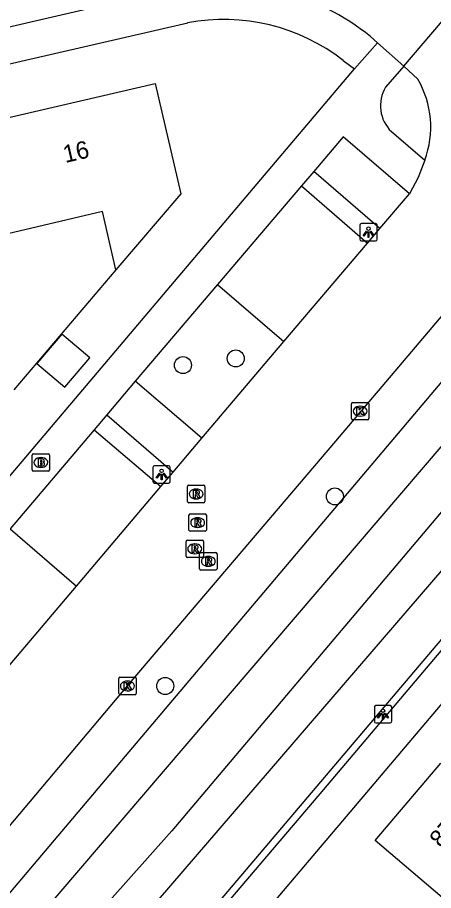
# Model space of a CAD drawing. Extents: x 156414 to 157775, y 382335 to 383765.
# Drawn here: x 156837.1 to 156861, y 382528.4 to 382578.5 of the extents above; entities that cross this region are included whole.
import ezdxf

# ---------------------------------------------------------------- set-up
doc = ezdxf.new("R2010")
doc.units = 0
for name, color, linetype in [('IMGEO_Boom', 7, 'Continuous'), ('IMGEO_Brandkraan', 7, 'Continuous'), ('IMGEO_Groenvoorziening', 7, 'Continuous'), ('IMGEO_Haag', 7, 'Continuous'), ('IMGEO_Kolk', 7, 'Continuous'), ('IMGEO_Lichtpunt', 7, 'Continuous'), ('IMGEO_Muur', 7, 'Continuous'), ('IMGEO_Pand', 7, 'Continuous'), ('IMGEO_Pand_nummerreeks', 7, 'Continuous'), ('IMGEO_Parkeervlak_open', 7, 'Continuous'), ('IMGEO_Rijbaan_lokaal_gesloten', 7, 'Continuous'), ('IMGEO_Rioolput', 7, 'Continuous'), ('IMGEO_Voetpad_open', 7, 'Continuous'), ('IMGEO_Waterloop', 7, 'Continuous')]:
    doc.layers.add(name, color=color, linetype=linetype)

msp = doc.modelspace()

# ---------------------------------------------------------------- linework, layer by layer
at = {"layer": 'IMGEO_Boom'}
for centre in [(156849.67, 382558.967), (156846.64, 382558.585), (156855.363, 382551.053), (156845.62, 382540.18)]:
    msp.add_circle(centre, 0.489, dxfattribs=at)
at = {"layer": 'IMGEO_Brandkraan'}
for p, q in [((156837.98, 382552.575), (156837.98, 382553.427)), ((156838.055, 382553.501), (156838.907, 382553.501)), ((156838.468, 382553.281), (156838.493, 382553.281)), ((156838.981, 382553.427), (156838.981, 382552.575)), ((156838.491, 382552.721), (156838.466, 382552.721)), ((156838.907, 382552.501), (156838.055, 382552.501))]:
    msp.add_line(p, q, dxfattribs=at)
for points in [[(156837.98, 382552.575), (156837.98, 382553.427)], [(156838.055, 382553.501), (156838.907, 382553.501)], [(156838.328, 382553.201), (156838.328, 382552.801), (156838.541, 382552.801)], [(156838.559, 382553.201), (156838.328, 382553.201)], [(156838.507, 382553.12), (156838.453, 382553.12), (156838.453, 382553.044)], [(156838.981, 382553.427), (156838.981, 382552.575)], [(156838.453, 382553.044), (156838.506, 382553.044)], [(156838.515, 382552.968), (156838.453, 382552.968), (156838.453, 382552.887)], [(156838.453, 382552.887), (156838.515, 382552.887)], [(156838.907, 382552.501), (156838.055, 382552.501)]]:
    msp.add_lwpolyline(points, dxfattribs=at)
for centre, radius, start, end in [((156838.057, 382553.425), 0.0765, 91.552, 178.448), ((156838.057, 382553.425), 0.0765, 91.552, 178.448), ((156838.508, 382553.082), 0.0379, 267.8285, 90.9355), ((156838.563, 382553.056), 0.145, 59.4692, 91.5367), ((156838.588, 382553.103), 0.0922, 285.5137, 58.1501), ((156838.905, 382553.425), 0.0765, 1.552, 88.448), ((156838.905, 382553.425), 0.0765, 1.552, 88.448), ((156838.516, 382552.927), 0.0404, 269.8759, 90.5077), ((156838.547, 382553.052), 0.251, 268.6676, 293.5347), ((156838.593, 382552.911), 0.105, 301.3115, 78.989), ((156838.057, 382552.577), 0.0765, 181.552, 268.448), ((156838.057, 382552.577), 0.0765, 181.552, 268.448), ((156838.905, 382552.577), 0.0765, 271.552, 358.448), ((156838.905, 382552.577), 0.0765, 271.552, 358.448)]:
    msp.add_arc(centre, radius, start, end, dxfattribs=at)
for centre, major_axis, ratio, start_param, end_param in [((156838.467, 382553.001), (-0.387, 0.002), 0.722429, 4.712389, 7.853982), ((156838.492, 382553.001), (-0.39, 0.002), 0.717154, 1.570796, 4.712389)]:
    msp.add_ellipse(centre, major_axis=major_axis, ratio=ratio, start_param=start_param, end_param=end_param, dxfattribs=at)
at = {"layer": 'IMGEO_Groenvoorziening'}
for points in [[(156883.467, 382582.632), (156865.157, 382561.969), (156834.624, 382525.907), (156833.429, 382523.914), (156832.515, 382522.224)], [(156836.701, 382518.344), (156839.563, 382521.34), (156866.603, 382552.72), (156888.158, 382578.673)]]:
    msp.add_lwpolyline(points, dxfattribs=at)
at = {"layer": 'IMGEO_Haag'}
msp.add_lwpolyline([(156890.335, 382576.835), (156839.257, 382516.694), (156839.538, 382516.434), (156839.658, 382516.575)], dxfattribs=at)
at = {"layer": 'IMGEO_Kolk'}
for p, q in [((156856.311, 382555.52), (156856.311, 382556.372)), ((156856.386, 382556.446), (156857.238, 382556.446)), ((156856.799, 382556.226), (156856.824, 382556.226)), ((156857.312, 382556.372), (156857.312, 382555.52)), ((156856.822, 382555.666), (156856.797, 382555.666)), ((156857.238, 382555.446), (156856.386, 382555.446)), ((156842.947, 382539.757), (156842.947, 382540.609)), ((156843.022, 382540.683), (156843.874, 382540.683)), ((156843.948, 382540.609), (156843.948, 382539.757)), ((156843.435, 382540.463), (156843.46, 382540.463)), ((156843.874, 382539.683), (156843.022, 382539.683)), ((156843.458, 382539.903), (156843.433, 382539.903))]:
    msp.add_line(p, q, dxfattribs=at)
for points in [[(156856.311, 382555.52), (156856.311, 382556.372)], [(156856.386, 382556.446), (156857.238, 382556.446)], [(156856.632, 382556.146), (156856.755, 382556.146), (156856.755, 382555.995), (156856.885, 382556.146), (156857.049, 382556.146), (156856.903, 382555.995), (156857.056, 382555.746), (156856.904, 382555.746), (156856.819, 382555.91), (156856.755, 382555.843), (156856.755, 382555.746), (156856.632, 382555.746), (156856.632, 382556.146)], [(156857.312, 382556.372), (156857.312, 382555.52)], [(156857.238, 382555.446), (156856.386, 382555.446)], [(156842.947, 382539.757), (156842.947, 382540.609)], [(156843.022, 382540.683), (156843.874, 382540.683)], [(156843.948, 382540.609), (156843.948, 382539.757)], [(156843.268, 382540.383), (156843.391, 382540.383), (156843.391, 382540.232), (156843.521, 382540.383), (156843.685, 382540.383), (156843.539, 382540.232), (156843.692, 382539.983), (156843.54, 382539.983), (156843.455, 382540.147), (156843.391, 382540.08), (156843.391, 382539.983), (156843.268, 382539.983), (156843.268, 382540.383)], [(156843.874, 382539.683), (156843.022, 382539.683)]]:
    msp.add_lwpolyline(points, dxfattribs=at)
for centre, start, end in [((156856.388, 382556.37), 91.552, 178.448), ((156856.388, 382556.37), 91.552, 178.448), ((156857.236, 382556.37), 1.552, 88.448), ((156857.236, 382556.37), 1.552, 88.448), ((156856.388, 382555.522), 181.552, 268.448), ((156856.388, 382555.522), 181.552, 268.448), ((156857.236, 382555.522), 271.552, 358.448), ((156857.236, 382555.522), 271.552, 358.448), ((156843.024, 382540.607), 91.552, 178.448), ((156843.024, 382540.607), 91.552, 178.448), ((156843.872, 382540.607), 1.552, 88.448), ((156843.872, 382540.607), 1.552, 88.448), ((156843.024, 382539.759), 181.552, 268.448), ((156843.024, 382539.759), 181.552, 268.448), ((156843.872, 382539.759), 271.552, 358.448), ((156843.872, 382539.759), 271.552, 358.448)]:
    msp.add_arc(centre, 0.0765, start, end, dxfattribs=at)
for centre, major_axis, ratio, start_param, end_param in [((156856.798, 382555.946), (-0.387, 0.002), 0.722429, 4.712389, 7.853982), ((156856.823, 382555.946), (-0.39, 0.002), 0.717154, 1.570796, 4.712389), ((156843.434, 382540.183), (-0.387, 0.002), 0.722429, 4.712389, 7.853982), ((156843.459, 382540.183), (-0.39, 0.002), 0.717154, 1.570796, 4.712389)]:
    msp.add_ellipse(centre, major_axis=major_axis, ratio=ratio, start_param=start_param, end_param=end_param, dxfattribs=at)
at = {"layer": 'IMGEO_Lichtpunt'}
for p, q in [((156857.698, 382566.708), (156856.89, 382566.708)), ((156857.698, 382566.708), (156856.89, 382566.708)), ((156856.796, 382566.613), (156856.796, 382565.806)), ((156856.796, 382566.613), (156856.796, 382565.806)), ((156857.792, 382565.806), (156857.792, 382566.613)), ((156857.792, 382565.806), (156857.792, 382566.613)), ((156856.89, 382565.712), (156857.698, 382565.712)), ((156856.89, 382565.712), (156857.698, 382565.712)), ((156844.913, 382552.721), (156844.913, 382551.914)), ((156844.913, 382552.721), (156844.913, 382551.914)), ((156845.815, 382552.816), (156845.007, 382552.816)), ((156845.815, 382552.816), (156845.007, 382552.816)), ((156845.909, 382551.914), (156845.909, 382552.721)), ((156845.909, 382551.914), (156845.909, 382552.721)), ((156845.007, 382551.82), (156845.815, 382551.82)), ((156845.007, 382551.82), (156845.815, 382551.82)), ((156857.629, 382538.966), (156857.629, 382538.159)), ((156857.629, 382538.966), (156857.629, 382538.159)), ((156858.531, 382539.061), (156857.723, 382539.061)), ((156858.531, 382539.061), (156857.723, 382539.061)), ((156858.625, 382538.159), (156858.625, 382538.966)), ((156858.625, 382538.159), (156858.625, 382538.966)), ((156857.723, 382538.065), (156858.531, 382538.065)), ((156857.723, 382538.065), (156858.531, 382538.065))]:
    msp.add_line(p, q, dxfattribs=at)
for points in [[(156857.17, 382566.277), (156857.209, 382566.249), (156857.021, 382565.987), (156856.983, 382566.014), (156857.17, 382566.277)], [(156857.272, 382566.229), (156857.319, 382566.229), (156857.319, 382565.907), (156857.272, 382565.907), (156857.272, 382566.229)], [(156857.382, 382566.249), (156857.42, 382566.276), (156857.607, 382566.014), (156857.568, 382565.986), (156857.382, 382566.249)], [(156845.287, 382552.385), (156845.326, 382552.357), (156845.138, 382552.095), (156845.1, 382552.122), (156845.287, 382552.385)], [(156845.389, 382552.337), (156845.436, 382552.337), (156845.436, 382552.015), (156845.389, 382552.015), (156845.389, 382552.337)], [(156845.499, 382552.357), (156845.537, 382552.384), (156845.724, 382552.122), (156845.685, 382552.094), (156845.499, 382552.357)], [(156858.003, 382538.63), (156858.042, 382538.602), (156857.854, 382538.34), (156857.816, 382538.367), (156858.003, 382538.63)], [(156858.215, 382538.602), (156858.253, 382538.629), (156858.44, 382538.367), (156858.401, 382538.339), (156858.215, 382538.602)], [(156858.105, 382538.582), (156858.152, 382538.582), (156858.152, 382538.26), (156858.105, 382538.26), (156858.105, 382538.582)]]:
    msp.add_lwpolyline(points, dxfattribs=at)
for centre in [(156857.295, 382566.411), (156845.412, 382552.519), (156858.128, 382538.764)]:
    msp.add_circle(centre, 0.0994, dxfattribs=at)
for centre, start, end in [((156856.89, 382566.613), 90, 180), ((156856.89, 382566.613), 90, 180), ((156857.698, 382566.613), 0, 90), ((156857.698, 382566.613), 0, 90), ((156856.89, 382565.806), 180, 270), ((156856.89, 382565.806), 180, 270), ((156857.698, 382565.806), 270, 0), ((156857.698, 382565.806), 270, 360), ((156845.007, 382552.721), 90, 180), ((156845.007, 382552.721), 90, 180), ((156845.815, 382552.721), 0, 90), ((156845.815, 382552.721), 0, 90), ((156845.007, 382551.914), 180, 270), ((156845.007, 382551.914), 180, 270), ((156845.815, 382551.914), 270, 0), ((156845.815, 382551.914), 270, 360), ((156857.723, 382538.966), 90, 180), ((156857.723, 382538.966), 90, 180), ((156858.531, 382538.966), 0, 90), ((156858.531, 382538.966), 0, 90), ((156857.723, 382538.159), 180, 270), ((156857.723, 382538.159), 180, 270), ((156858.531, 382538.159), 270, 0), ((156858.531, 382538.159), 270, 360)]:
    msp.add_arc(centre, 0.0946, start, end, dxfattribs=at)
at = {"layer": 'IMGEO_Muur'}
msp.add_lwpolyline([(156842.791, 382564.053), (156836.926, 382557.168)], dxfattribs=at)
at = {"layer": 'IMGEO_Pand'}
for points in [[(156835.122, 382572.451), (156845.049, 382574.744), (156846.509, 382568.408), (156842.791, 382564.053), (156842.016, 382567.39), (156836.576, 382566.122)], [(156838.256, 382558.675), (156839.859, 382557.315), (156841.294, 382559.006), (156839.692, 382560.366), (156838.256, 382558.675)], [(156869.14, 382529.214), (156865.381, 382524.784), (156857.671, 382531.315), (156861.441, 382535.754)]]:
    msp.add_lwpolyline(points, dxfattribs=at)
at = {"layer": 'IMGEO_Parkeervlak_open'}
for points in [[(156848.622, 382563.205), (156852.423, 382559.947)], [(156847.72, 382554.39), (156843.897, 382557.663)], [(156836.723, 382549.204), (156840.532, 382545.9)]]:
    msp.add_lwpolyline(points, dxfattribs=at)
at = {"layer": 'IMGEO_Rijbaan_lokaal_gesloten'}
for points in [[(156881.147, 382584.59), (156855.391, 382554.226), (156843.769, 382540.567), (156831.328, 382525.852), (156828.33, 382522.305), (156828.27, 382522.229), (156828.21, 382522.153)], [(156846.459, 382580.188), (156845.95, 382580.133), (156762.402, 382560.842)], [(156859.329, 382575.743), (156862.534, 382579.499)], [(156857.81, 382577.079), (156857.405, 382577.435)], [(156857.81, 382577.079), (156859.329, 382575.743)], [(156860.125, 382574.983), (156859.329, 382575.743)], [(156860.522, 382570.35), (156860.138, 382569.338), (156859.65, 382568.411)], [(156857.952, 382566.422), (156859.65, 382568.411)], [(156857.228, 382565.575), (156857.952, 382566.422)], [(156852.423, 382559.947), (156857.228, 382565.575)], [(156847.72, 382554.39), (156852.423, 382559.947)], [(156846.072, 382552.444), (156847.72, 382554.39)], [(156845.373, 382551.618), (156846.072, 382552.444)], [(156840.532, 382545.9), (156845.373, 382551.618)], [(156836.503, 382541.171), (156840.532, 382545.9)]]:
    msp.add_lwpolyline(points, dxfattribs=at)
for centre, radius, start, end in [((156848.965, 382567.013), 13.411, 50.9975, 100.7675), ((156855.491, 382572.252), 5.379, 339.2865, 30.5088)]:
    msp.add_arc(centre, radius, start, end, dxfattribs=at)
at = {"layer": 'IMGEO_Rioolput'}
for p, q in [((156846.895, 382550.768), (156846.895, 382551.62)), ((156846.97, 382551.694), (156847.822, 382551.694)), ((156847.896, 382551.62), (156847.896, 382550.768)), ((156847.383, 382551.474), (156847.408, 382551.474)), ((156847.822, 382550.694), (156846.97, 382550.694)), ((156847.406, 382550.914), (156847.381, 382550.914)), ((156846.982, 382549.127), (156846.982, 382549.979)), ((156847.057, 382550.053), (156847.909, 382550.053)), ((156847.47, 382549.833), (156847.495, 382549.833)), ((156847.983, 382549.979), (156847.983, 382549.127)), ((156847.493, 382549.273), (156847.468, 382549.273)), ((156847.909, 382549.053), (156847.057, 382549.053)), ((156846.814, 382547.623), (156846.814, 382548.475)), ((156846.889, 382548.549), (156847.741, 382548.549)), ((156847.302, 382548.329), (156847.327, 382548.329)), ((156847.815, 382548.475), (156847.815, 382547.623)), ((156847.325, 382547.769), (156847.3, 382547.769)), ((156847.594, 382546.906), (156847.594, 382547.758)), ((156847.669, 382547.832), (156848.521, 382547.832)), ((156848.082, 382547.612), (156848.107, 382547.612)), ((156848.595, 382547.758), (156848.595, 382546.906)), ((156847.741, 382547.549), (156846.889, 382547.549)), ((156848.521, 382546.832), (156847.669, 382546.832)), ((156848.105, 382547.052), (156848.08, 382547.052))]:
    msp.add_line(p, q, dxfattribs=at)
for points in [[(156846.895, 382550.768), (156846.895, 382551.62)], [(156846.97, 382551.694), (156847.822, 382551.694)], [(156847.896, 382551.62), (156847.896, 382550.768)], [(156847.484, 382551.392), (156847.232, 382551.394), (156847.232, 382550.994)], [(156847.232, 382550.994), (156847.356, 382550.994), (156847.356, 382551.156), (156847.367, 382551.156)], [(156847.41, 382551.313), (156847.356, 382551.313), (156847.356, 382551.232)], [(156847.356, 382551.232), (156847.408, 382551.232)], [(156847.414, 382551.127), (156847.485, 382550.994), (156847.625, 382550.994), (156847.56, 382551.12)], [(156847.822, 382550.694), (156846.97, 382550.694)], [(156846.982, 382549.127), (156846.982, 382549.979)], [(156847.057, 382550.053), (156847.909, 382550.053)], [(156847.571, 382549.751), (156847.319, 382549.753), (156847.319, 382549.353)], [(156847.497, 382549.672), (156847.443, 382549.672), (156847.443, 382549.591)], [(156847.983, 382549.979), (156847.983, 382549.127)], [(156847.319, 382549.353), (156847.443, 382549.353), (156847.443, 382549.515), (156847.454, 382549.515)], [(156847.443, 382549.591), (156847.495, 382549.591)], [(156847.501, 382549.486), (156847.572, 382549.353), (156847.712, 382549.353), (156847.647, 382549.479)], [(156847.909, 382549.053), (156847.057, 382549.053)], [(156846.814, 382547.623), (156846.814, 382548.475)], [(156846.889, 382548.549), (156847.741, 382548.549)], [(156847.403, 382548.247), (156847.151, 382548.249), (156847.151, 382547.849)], [(156847.329, 382548.168), (156847.275, 382548.168), (156847.275, 382548.087)], [(156847.815, 382548.475), (156847.815, 382547.623)], [(156847.151, 382547.849), (156847.275, 382547.849), (156847.275, 382548.011), (156847.286, 382548.011)], [(156847.275, 382548.087), (156847.327, 382548.087)], [(156847.333, 382547.982), (156847.404, 382547.849), (156847.544, 382547.849), (156847.479, 382547.975)], [(156847.594, 382546.906), (156847.594, 382547.758)], [(156847.669, 382547.832), (156848.521, 382547.832)], [(156848.595, 382547.758), (156848.595, 382546.906)], [(156847.741, 382547.549), (156846.889, 382547.549)], [(156848.183, 382547.53), (156847.931, 382547.532), (156847.931, 382547.132)], [(156847.931, 382547.132), (156848.055, 382547.132), (156848.055, 382547.294), (156848.066, 382547.294)], [(156848.109, 382547.451), (156848.055, 382547.451), (156848.055, 382547.37)], [(156848.055, 382547.37), (156848.107, 382547.37)], [(156848.113, 382547.265), (156848.184, 382547.132), (156848.324, 382547.132), (156848.259, 382547.258)], [(156848.521, 382546.832), (156847.669, 382546.832)]]:
    msp.add_lwpolyline(points, dxfattribs=at)
for centre, radius, start, end in [((156846.972, 382551.618), 0.0765, 91.552, 178.448), ((156846.972, 382551.618), 0.0765, 91.552, 178.448), ((156847.82, 382551.618), 0.0765, 1.552, 88.448), ((156847.82, 382551.618), 0.0765, 1.552, 88.448), ((156847.366, 382551.103), 0.0533, 26.0293, 88.6989), ((156847.392, 382551.421), 0.19, 274.7715, 282.9687), ((156847.416, 382551.217), 0.0964, 77.0061, 93.1865), ((156847.43, 382551.274), 0.0378, 276.6634, 79.6772), ((156847.483, 382551.282), 0.109, 350.3612, 89.416), ((156847.481, 382551.282), 0.112, 277.5842, 350.9817), ((156847.465, 382551.067), 0.108, 29.5134, 73.7905), ((156846.972, 382550.77), 0.0765, 181.552, 268.448), ((156846.972, 382550.77), 0.0765, 181.552, 268.448), ((156847.82, 382550.77), 0.0765, 271.552, 358.448), ((156847.82, 382550.77), 0.0765, 271.552, 358.448), ((156847.059, 382549.977), 0.0765, 91.552, 178.448), ((156847.059, 382549.977), 0.0765, 91.552, 178.448), ((156847.503, 382549.576), 0.0964, 77.0061, 93.1865), ((156847.517, 382549.633), 0.0378, 276.6634, 79.6772), ((156847.57, 382549.641), 0.109, 350.3612, 89.416), ((156847.568, 382549.641), 0.112, 277.5842, 350.9817), ((156847.907, 382549.977), 0.0765, 1.552, 88.448), ((156847.907, 382549.977), 0.0765, 1.552, 88.448), ((156847.059, 382549.129), 0.0765, 181.552, 268.448), ((156847.059, 382549.129), 0.0765, 181.552, 268.448), ((156847.453, 382549.462), 0.0533, 26.0293, 88.6989), ((156847.479, 382549.78), 0.19, 274.7715, 282.9687), ((156847.552, 382549.426), 0.108, 29.5134, 73.7905), ((156847.907, 382549.129), 0.0765, 271.552, 358.448), ((156847.907, 382549.129), 0.0765, 271.552, 358.448), ((156846.891, 382548.473), 0.0765, 91.552, 178.448), ((156846.891, 382548.473), 0.0765, 91.552, 178.448), ((156847.335, 382548.072), 0.0964, 77.0061, 93.1865), ((156847.349, 382548.129), 0.0378, 276.6634, 79.6772), ((156847.402, 382548.137), 0.109, 350.3612, 89.416), ((156847.4, 382548.137), 0.112, 277.5842, 350.9817), ((156847.739, 382548.473), 0.0765, 1.552, 88.448), ((156847.739, 382548.473), 0.0765, 1.552, 88.448), ((156846.891, 382547.625), 0.0765, 181.552, 268.448), ((156846.891, 382547.625), 0.0765, 181.552, 268.448), ((156847.285, 382547.958), 0.0533, 26.0293, 88.6989), ((156847.311, 382548.276), 0.19, 274.7715, 282.9687), ((156847.384, 382547.922), 0.108, 29.5134, 73.7905), ((156847.671, 382547.756), 0.0765, 91.552, 178.448), ((156847.671, 382547.756), 0.0765, 91.552, 178.448), ((156847.739, 382547.625), 0.0765, 271.552, 358.448), ((156847.739, 382547.625), 0.0765, 271.552, 358.448), ((156848.519, 382547.756), 0.0765, 1.552, 88.448), ((156848.519, 382547.756), 0.0765, 1.552, 88.448), ((156848.065, 382547.241), 0.0533, 26.0293, 88.6989), ((156848.091, 382547.559), 0.19, 274.7715, 282.9687), ((156848.115, 382547.355), 0.0964, 77.0061, 93.1865), ((156848.129, 382547.412), 0.0378, 276.6634, 79.6772), ((156848.182, 382547.42), 0.109, 350.3612, 89.416), ((156848.18, 382547.42), 0.112, 277.5842, 350.9817), ((156848.164, 382547.205), 0.108, 29.5134, 73.7905), ((156847.671, 382546.908), 0.0765, 181.552, 268.448), ((156847.671, 382546.908), 0.0765, 181.552, 268.448), ((156848.519, 382546.908), 0.0765, 271.552, 358.448), ((156848.519, 382546.908), 0.0765, 271.552, 358.448)]:
    msp.add_arc(centre, radius, start, end, dxfattribs=at)
for centre, major_axis, ratio, start_param, end_param in [((156847.382, 382551.194), (-0.387, 0.002), 0.722429, 4.712389, 7.853982), ((156847.407, 382551.194), (-0.39, 0.002), 0.717154, 1.570796, 4.712389), ((156847.469, 382549.553), (-0.387, 0.002), 0.722429, 4.712389, 7.853982), ((156847.494, 382549.553), (-0.39, 0.002), 0.717154, 1.570796, 4.712389), ((156847.301, 382548.049), (-0.387, 0.002), 0.722429, 4.712389, 7.853982), ((156847.326, 382548.049), (-0.39, 0.002), 0.717154, 1.570796, 4.712389), ((156848.081, 382547.332), (-0.387, 0.002), 0.722429, 4.712389, 7.853982), ((156848.106, 382547.332), (-0.39, 0.002), 0.717154, 1.570796, 4.712389)]:
    msp.add_ellipse(centre, major_axis=major_axis, ratio=ratio, start_param=start_param, end_param=end_param, dxfattribs=at)
at = {"layer": 'IMGEO_Voetpad_open'}
for points in [[(156805.533, 382568.712), (156846.909, 382578.224)], [(156890.335, 382576.835), (156890.6, 382576.611), (156854.504, 382533.997), (156841.596, 382518.849)], [(156856.496, 382575.585), (156857.81, 382577.079)], [(156855.848, 382576.066), (156856.496, 382575.585)], [(156859.329, 382575.743), (156858.275, 382574.531)], [(156784.875, 382491.099), (156856.496, 382575.585)], [(156859.65, 382568.411), (156855.833, 382571.681), (156854.147, 382569.699)], [(156858.613, 382571.978), (156860.522, 382570.35)], [(156854.147, 382569.699), (156853.438, 382568.866)], [(156857.952, 382566.422), (156854.147, 382569.699)], [(156853.438, 382568.866), (156848.622, 382563.205)], [(156853.438, 382568.866), (156857.228, 382565.575)], [(156848.622, 382563.205), (156843.897, 382557.663)], [(156843.897, 382557.663), (156842.26, 382555.733)], [(156842.26, 382555.733), (156841.535, 382554.878)], [(156842.26, 382555.733), (156846.072, 382552.444)], [(156841.535, 382554.878), (156836.723, 382549.204)], [(156841.535, 382554.878), (156845.373, 382551.618)], [(156843.15, 382517.517), (156856.03, 382532.704), (156871.178, 382550.544)]]:
    msp.add_lwpolyline(points, dxfattribs=at)
for centre, radius, start, end in [((156848.96, 382567.128), 11.284, 52.381, 100.4744), ((156860.043, 382573.466), 2.064, 148.9403, 226.1431)]:
    msp.add_arc(centre, radius, start, end, dxfattribs=at)
at = {"layer": 'IMGEO_Waterloop'}
msp.add_lwpolyline([(156885.526, 382578.584), (156845.993, 382531.875), (156836.354, 382521.047), (156834.528, 382522.47), (156883.743, 382579.943), (156885.526, 382578.584)], dxfattribs=at)

# ---------------------------------------------------------------- texts
at = {"layer": 'IMGEO_Pand_nummerreeks'}
for s, rotation, p in [('16', 13.0076, (156839.879, 382570.178)), ('87', 49.9297, (156861.472, 382530.84))]:
    msp.add_text(s, height=1, rotation=rotation, dxfattribs=at).set_placement(p)

doc.saveas('drawing.dxf')
